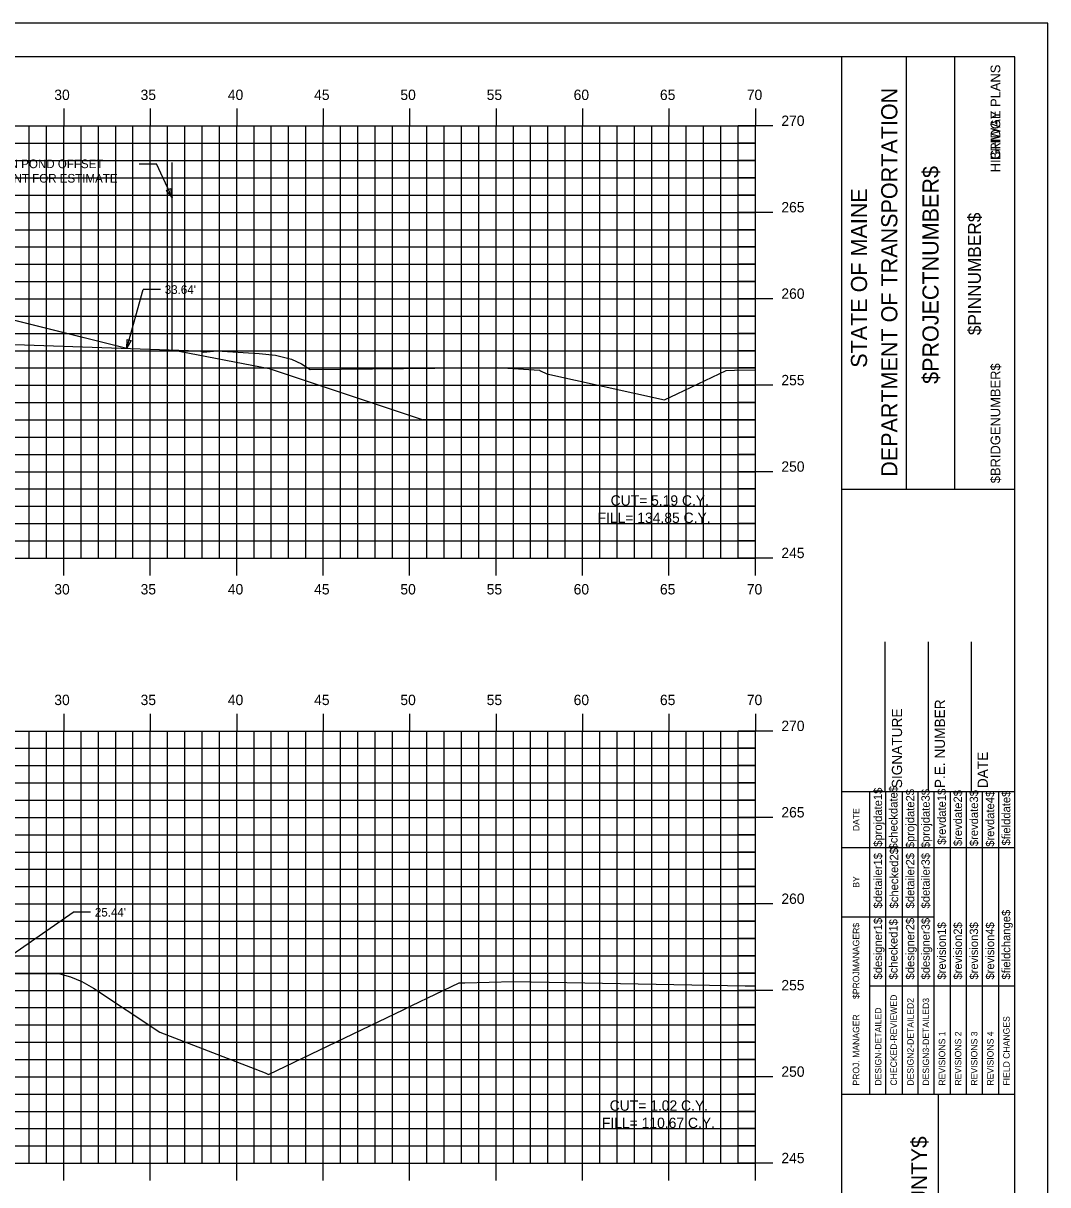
# Model space of a CAD drawing. Extents: x 1170543 to 1177585, y 609599 to 610623.
# Drawn here: x 1175606.5 to 1175665.7, y 609641.6 to 609708.8 of the extents above; entities that cross this region are included whole.
import ezdxf

# ---------------------------------------------------------------- set-up
doc = ezdxf.new("R2010")
doc.units = 0
for name, color, linetype in [('ANNOTATION', 7, 'Continuous'), ('BORDER', 7, 'Continuous'), ('BRIDGE_TITLE', 7, 'Continuous'), ('D_Roadway_Centerline', 7, 'Continuous'), ('D_Roadway_Centerline_Text', 7, 'Continuous'), ('D_Roadway_Edge_Pavement', 7, 'Continuous'), ('D_Roadway_Pavement', 7, 'Continuous'), ('D_Roadway_SlopeLines', 7, 'Continuous'), ('H_V ANNOTATION', 7, 'Continuous'), ('HIGHWAY_TITLE', 7, 'Continuous'), ('MAJOR', 7, 'Continuous'), ('MINOR', 7, 'Continuous'), ('PLOT BOUNDARY', 7, 'Continuous'), ('S_Roadway_Centerline', 7, 'Continuous')]:
    doc.layers.add(name, color=color, linetype=linetype)

msp = doc.modelspace()

# ---------------------------------------------------------------- linework, layer by layer
at = {"layer": 'ANNOTATION'}
for p, q in [((1175613.193, 609700.68), (1175614.193, 609700.68)), ((1175615.096, 609698.739), (1175614.193, 609700.68)), ((1175612.469, 609690.009), (1175613.414, 609693.408)), ((1175614.414, 609693.408), (1175613.414, 609693.408)), ((1175604.272, 609653.849), (1175609.374, 609657.391)), ((1175610.374, 609657.391), (1175609.374, 609657.391))]:
    msp.add_line(p, q, dxfattribs=at)
for points in [[(1175614.999, 609699.245), (1175615.096, 609698.739), (1175614.772, 609699.14)], [(1175612.723, 609690.457), (1175612.469, 609690.009), (1175612.483, 609690.524)]]:
    msp.add_lwpolyline(points, close=True, dxfattribs=at)
at = {"layer": 'BORDER'}
for p, q in [((1175663.826, 609706.872), (1175503.826, 609706.872)), ((1175653.826, 609601.875), (1175653.826, 609706.875)), ((1175657.555, 609681.869), (1175657.555, 609706.869)), ((1175660.35, 609681.869), (1175660.35, 609706.869)), ((1175663.826, 609601.875), (1175663.826, 609706.875)), ((1175653.827, 609681.866), (1175663.826, 609681.866)), ((1175656.326, 609664.375), (1175656.326, 609673.023)), ((1175658.826, 609664.375), (1175658.826, 609673.023)), ((1175661.326, 609664.375), (1175661.326, 609673.023)), ((1175653.826, 609664.375), (1175663.826, 609664.375)), ((1175653.826, 609646.875), (1175663.826, 609646.875)), ((1175659.417, 609611.875), (1175659.417, 609646.875))]:
    msp.add_line(p, q, dxfattribs=at)
for points in [[(1175655.441, 609661.125), (1175655.441, 609664.375)], [(1175656.374, 609646.878), (1175656.374, 609664.375)], [(1175657.305, 609664.375), (1175657.305, 609646.878)], [(1175658.237, 609646.878), (1175658.237, 609664.375)], [(1175659.169, 609646.878), (1175659.169, 609664.375)], [(1175660.101, 609646.878), (1175660.101, 609664.375)], [(1175661.032, 609646.878), (1175661.032, 609664.375)], [(1175661.964, 609646.878), (1175661.964, 609664.375)], [(1175662.896, 609646.878), (1175662.896, 609664.375)], [(1175655.442, 609646.878), (1175655.442, 609663.669)], [(1175653.826, 609661.125), (1175663.826, 609661.125)], [(1175653.826, 609657.125), (1175655.442, 609657.125)], [(1175655.441, 609657.125), (1175659.168, 609657.125)], [(1175655.441, 609653.125), (1175663.826, 609653.125)]]:
    msp.add_lwpolyline(points, dxfattribs=at)
at = {"layer": 'D_Roadway_Centerline'}
for p, q in [((1175597.826, 609693.67), (1175606.919, 609691.397)), ((1175606.919, 609691.397), (1175612.469, 609690.009))]:
    msp.add_line(p, q, dxfattribs=at)
at = {"layer": 'D_Roadway_Edge_Pavement'}
msp.add_line((1175648.826, 609685.872), (1175629.617, 609685.872), dxfattribs=at)
msp.add_lwpolyline([(1175615.096, 609689.92), (1175620.706, 609688.839), (1175621.974, 609688.417), (1175623.709, 609687.839), (1175624.986, 609687.414), (1175626.712, 609686.839), (1175629.617, 609685.872)], dxfattribs=at)
at = {"layer": 'D_Roadway_Pavement'}
msp.add_line((1175615.096, 609689.925), (1175615.096, 609700.765), dxfattribs=at)
at = {"layer": 'D_Roadway_SlopeLines'}
msp.add_lwpolyline([(1175597.826, 609693.67), (1175612.469, 609690.009)], dxfattribs=at)
at = {"layer": 'MAJOR'}
for p, q in [((1175608.826, 609703.874), (1175608.826, 609702.872)), ((1175613.826, 609703.874), (1175613.826, 609702.872)), ((1175618.826, 609703.874), (1175618.826, 609702.872)), ((1175623.826, 609703.874), (1175623.826, 609702.872)), ((1175628.826, 609703.874), (1175628.826, 609702.872)), ((1175633.826, 609703.874), (1175633.826, 609702.872)), ((1175638.826, 609703.874), (1175638.826, 609702.872)), ((1175643.826, 609703.874), (1175643.826, 609702.872)), ((1175648.826, 609703.874), (1175648.826, 609702.872)), ((1175508.826, 609702.872), (1175648.826, 609702.872)), ((1175508.826, 609702.872), (1175648.826, 609702.872)), ((1175608.826, 609677.872), (1175608.826, 609702.872)), ((1175613.826, 609677.872), (1175613.826, 609702.872)), ((1175618.826, 609677.872), (1175618.826, 609702.872)), ((1175623.826, 609677.872), (1175623.826, 609702.872)), ((1175628.826, 609677.872), (1175628.826, 609702.872)), ((1175633.826, 609677.872), (1175633.826, 609702.872)), ((1175638.826, 609677.872), (1175638.826, 609702.872)), ((1175643.826, 609677.872), (1175643.826, 609702.872)), ((1175649.828, 609702.872), (1175647.824, 609702.872)), ((1175648.826, 609677.872), (1175648.826, 609702.872)), ((1175648.826, 609677.872), (1175648.826, 609702.872)), ((1175508.826, 609697.872), (1175648.826, 609697.872)), ((1175649.828, 609697.872), (1175647.824, 609697.872)), ((1175508.826, 609692.872), (1175648.826, 609692.872)), ((1175649.828, 609692.872), (1175647.824, 609692.872)), ((1175508.826, 609687.872), (1175648.826, 609687.872)), ((1175649.828, 609687.872), (1175647.824, 609687.872)), ((1175508.826, 609682.872), (1175648.826, 609682.872)), ((1175649.828, 609682.872), (1175647.824, 609682.872)), ((1175508.826, 609677.872), (1175648.826, 609677.872)), ((1175508.826, 609677.872), (1175648.826, 609677.872)), ((1175608.826, 609676.87), (1175608.826, 609677.872)), ((1175613.826, 609676.87), (1175613.826, 609677.872)), ((1175618.826, 609676.87), (1175618.826, 609677.872)), ((1175623.826, 609676.87), (1175623.826, 609677.872)), ((1175628.826, 609676.87), (1175628.826, 609677.872)), ((1175633.826, 609676.87), (1175633.826, 609677.872)), ((1175638.826, 609676.87), (1175638.826, 609677.872)), ((1175643.826, 609676.87), (1175643.826, 609677.872)), ((1175649.828, 609677.872), (1175647.824, 609677.872)), ((1175648.826, 609676.87), (1175648.826, 609677.872)), ((1175608.826, 609668.874), (1175608.826, 609667.872)), ((1175613.826, 609668.874), (1175613.826, 609667.872)), ((1175618.826, 609668.874), (1175618.826, 609667.872)), ((1175623.826, 609668.874), (1175623.826, 609667.872)), ((1175628.826, 609668.874), (1175628.826, 609667.872)), ((1175633.826, 609668.874), (1175633.826, 609667.872)), ((1175638.826, 609668.874), (1175638.826, 609667.872)), ((1175643.826, 609668.874), (1175643.826, 609667.872)), ((1175648.826, 609668.874), (1175648.826, 609667.872)), ((1175508.826, 609667.872), (1175648.826, 609667.872)), ((1175508.826, 609667.872), (1175648.826, 609667.872)), ((1175608.826, 609642.872), (1175608.826, 609667.872)), ((1175613.826, 609642.872), (1175613.826, 609667.872)), ((1175618.826, 609642.872), (1175618.826, 609667.872)), ((1175623.826, 609642.872), (1175623.826, 609667.872)), ((1175628.826, 609642.872), (1175628.826, 609667.872)), ((1175633.826, 609642.872), (1175633.826, 609667.872)), ((1175638.826, 609642.872), (1175638.826, 609667.872)), ((1175643.826, 609642.872), (1175643.826, 609667.872)), ((1175649.828, 609667.872), (1175647.824, 609667.872)), ((1175648.826, 609642.872), (1175648.826, 609667.872)), ((1175648.826, 609642.872), (1175648.826, 609667.872)), ((1175508.826, 609662.872), (1175648.826, 609662.872)), ((1175649.828, 609662.872), (1175647.824, 609662.872)), ((1175508.826, 609657.872), (1175648.826, 609657.872)), ((1175649.828, 609657.872), (1175647.824, 609657.872)), ((1175508.826, 609652.872), (1175648.826, 609652.872)), ((1175649.828, 609652.872), (1175647.824, 609652.872)), ((1175508.826, 609647.872), (1175648.826, 609647.872)), ((1175649.828, 609647.872), (1175647.824, 609647.872)), ((1175508.826, 609642.872), (1175648.826, 609642.872)), ((1175508.826, 609642.872), (1175648.826, 609642.872)), ((1175608.826, 609641.87), (1175608.826, 609642.872)), ((1175613.826, 609641.87), (1175613.826, 609642.872)), ((1175618.826, 609641.87), (1175618.826, 609642.872)), ((1175623.826, 609641.87), (1175623.826, 609642.872)), ((1175628.826, 609641.87), (1175628.826, 609642.872)), ((1175633.826, 609641.87), (1175633.826, 609642.872)), ((1175638.826, 609641.87), (1175638.826, 609642.872)), ((1175643.826, 609641.87), (1175643.826, 609642.872)), ((1175649.828, 609642.872), (1175647.824, 609642.872)), ((1175648.826, 609641.87), (1175648.826, 609642.872))]:
    msp.add_line(p, q, dxfattribs=at)
at = {"layer": 'MINOR'}
for p, q in [((1175606.826, 609677.872), (1175606.826, 609702.872)), ((1175607.826, 609677.872), (1175607.826, 609702.872)), ((1175609.826, 609677.872), (1175609.826, 609702.872)), ((1175610.826, 609677.872), (1175610.826, 609702.872)), ((1175611.826, 609677.872), (1175611.826, 609702.872)), ((1175612.826, 609677.872), (1175612.826, 609702.872)), ((1175614.826, 609677.872), (1175614.826, 609702.872)), ((1175615.826, 609677.872), (1175615.826, 609702.872)), ((1175616.826, 609677.872), (1175616.826, 609702.872)), ((1175617.826, 609677.872), (1175617.826, 609702.872)), ((1175619.826, 609677.872), (1175619.826, 609702.872)), ((1175620.826, 609677.872), (1175620.826, 609702.872)), ((1175621.826, 609677.872), (1175621.826, 609702.872)), ((1175622.826, 609677.872), (1175622.826, 609702.872)), ((1175624.826, 609677.872), (1175624.826, 609702.872)), ((1175625.826, 609677.872), (1175625.826, 609702.872)), ((1175626.826, 609677.872), (1175626.826, 609702.872)), ((1175627.826, 609677.872), (1175627.826, 609702.872)), ((1175629.826, 609677.872), (1175629.826, 609702.872)), ((1175630.826, 609677.872), (1175630.826, 609702.872)), ((1175631.826, 609677.872), (1175631.826, 609702.872)), ((1175632.826, 609677.872), (1175632.826, 609702.872)), ((1175634.826, 609677.872), (1175634.826, 609702.872)), ((1175635.826, 609677.872), (1175635.826, 609702.872)), ((1175636.826, 609677.872), (1175636.826, 609702.872)), ((1175637.826, 609677.872), (1175637.826, 609702.872)), ((1175639.826, 609677.872), (1175639.826, 609702.872)), ((1175640.826, 609677.872), (1175640.826, 609702.872)), ((1175641.826, 609677.872), (1175641.826, 609702.872)), ((1175642.826, 609677.872), (1175642.826, 609702.872)), ((1175644.826, 609677.872), (1175644.826, 609702.872)), ((1175645.826, 609677.872), (1175645.826, 609702.872)), ((1175646.826, 609677.872), (1175646.826, 609702.872)), ((1175647.826, 609677.872), (1175647.826, 609702.872)), ((1175508.826, 609701.872), (1175648.826, 609701.872)), ((1175648.826, 609701.872), (1175647.824, 609701.872)), ((1175508.826, 609700.872), (1175648.826, 609700.872)), ((1175648.826, 609700.872), (1175647.824, 609700.872)), ((1175508.826, 609699.872), (1175648.826, 609699.872)), ((1175648.826, 609699.872), (1175647.824, 609699.872)), ((1175508.826, 609698.872), (1175648.826, 609698.872)), ((1175648.826, 609698.872), (1175647.824, 609698.872)), ((1175508.826, 609696.872), (1175648.826, 609696.872)), ((1175648.826, 609696.872), (1175647.824, 609696.872)), ((1175508.826, 609695.872), (1175648.826, 609695.872)), ((1175648.826, 609695.872), (1175647.824, 609695.872)), ((1175508.826, 609694.872), (1175648.826, 609694.872)), ((1175648.826, 609694.872), (1175647.824, 609694.872)), ((1175508.826, 609693.872), (1175648.826, 609693.872)), ((1175648.826, 609693.872), (1175647.824, 609693.872)), ((1175508.826, 609691.872), (1175648.826, 609691.872)), ((1175648.826, 609691.872), (1175647.824, 609691.872)), ((1175508.826, 609690.872), (1175648.826, 609690.872)), ((1175648.826, 609690.872), (1175647.824, 609690.872)), ((1175508.826, 609689.872), (1175648.826, 609689.872)), ((1175648.826, 609689.872), (1175647.824, 609689.872)), ((1175508.826, 609688.872), (1175648.826, 609688.872)), ((1175648.826, 609688.872), (1175647.824, 609688.872)), ((1175508.826, 609686.872), (1175648.826, 609686.872)), ((1175648.826, 609686.872), (1175647.824, 609686.872)), ((1175508.826, 609685.872), (1175648.826, 609685.872)), ((1175648.826, 609685.872), (1175647.824, 609685.872)), ((1175508.826, 609684.872), (1175648.826, 609684.872)), ((1175648.826, 609684.872), (1175647.824, 609684.872)), ((1175508.826, 609683.872), (1175648.826, 609683.872)), ((1175648.826, 609683.872), (1175647.824, 609683.872)), ((1175508.826, 609681.872), (1175648.826, 609681.872)), ((1175648.826, 609681.872), (1175647.824, 609681.872)), ((1175508.826, 609680.872), (1175648.826, 609680.872)), ((1175648.826, 609680.872), (1175647.824, 609680.872)), ((1175508.826, 609679.872), (1175648.826, 609679.872)), ((1175648.826, 609679.872), (1175647.824, 609679.872)), ((1175508.826, 609678.872), (1175648.826, 609678.872)), ((1175648.826, 609678.872), (1175647.824, 609678.872)), ((1175606.826, 609642.872), (1175606.826, 609667.872)), ((1175607.826, 609642.872), (1175607.826, 609667.872)), ((1175609.826, 609642.872), (1175609.826, 609667.872)), ((1175610.826, 609642.872), (1175610.826, 609667.872)), ((1175611.826, 609642.872), (1175611.826, 609667.872)), ((1175612.826, 609642.872), (1175612.826, 609667.872)), ((1175614.826, 609642.872), (1175614.826, 609667.872)), ((1175615.826, 609642.872), (1175615.826, 609667.872)), ((1175616.826, 609642.872), (1175616.826, 609667.872)), ((1175617.826, 609642.872), (1175617.826, 609667.872)), ((1175619.826, 609642.872), (1175619.826, 609667.872)), ((1175620.826, 609642.872), (1175620.826, 609667.872)), ((1175621.826, 609642.872), (1175621.826, 609667.872)), ((1175622.826, 609642.872), (1175622.826, 609667.872)), ((1175624.826, 609642.872), (1175624.826, 609667.872)), ((1175625.826, 609642.872), (1175625.826, 609667.872)), ((1175626.826, 609642.872), (1175626.826, 609667.872)), ((1175627.826, 609642.872), (1175627.826, 609667.872)), ((1175629.826, 609642.872), (1175629.826, 609667.872)), ((1175630.826, 609642.872), (1175630.826, 609667.872)), ((1175631.826, 609642.872), (1175631.826, 609667.872)), ((1175632.826, 609642.872), (1175632.826, 609667.872)), ((1175634.826, 609642.872), (1175634.826, 609667.872)), ((1175635.826, 609642.872), (1175635.826, 609667.872)), ((1175636.826, 609642.872), (1175636.826, 609667.872)), ((1175637.826, 609642.872), (1175637.826, 609667.872)), ((1175639.826, 609642.872), (1175639.826, 609667.872)), ((1175640.826, 609642.872), (1175640.826, 609667.872)), ((1175641.826, 609642.872), (1175641.826, 609667.872)), ((1175642.826, 609642.872), (1175642.826, 609667.872)), ((1175644.826, 609642.872), (1175644.826, 609667.872)), ((1175645.826, 609642.872), (1175645.826, 609667.872)), ((1175646.826, 609642.872), (1175646.826, 609667.872)), ((1175647.826, 609642.872), (1175647.826, 609667.872)), ((1175508.826, 609666.872), (1175648.826, 609666.872)), ((1175648.826, 609666.872), (1175647.824, 609666.872)), ((1175508.826, 609665.872), (1175648.826, 609665.872)), ((1175648.826, 609665.872), (1175647.824, 609665.872)), ((1175508.826, 609664.872), (1175648.826, 609664.872)), ((1175648.826, 609664.872), (1175647.824, 609664.872)), ((1175508.826, 609663.872), (1175648.826, 609663.872)), ((1175648.826, 609663.872), (1175647.824, 609663.872)), ((1175508.826, 609661.872), (1175648.826, 609661.872)), ((1175648.826, 609661.872), (1175647.824, 609661.872)), ((1175508.826, 609660.872), (1175648.826, 609660.872)), ((1175648.826, 609660.872), (1175647.824, 609660.872)), ((1175508.826, 609659.872), (1175648.826, 609659.872)), ((1175648.826, 609659.872), (1175647.824, 609659.872)), ((1175508.826, 609658.872), (1175648.826, 609658.872)), ((1175648.826, 609658.872), (1175647.824, 609658.872)), ((1175508.826, 609656.872), (1175648.826, 609656.872)), ((1175648.826, 609656.872), (1175647.824, 609656.872)), ((1175508.826, 609655.872), (1175648.826, 609655.872)), ((1175648.826, 609655.872), (1175647.824, 609655.872)), ((1175508.826, 609654.872), (1175648.826, 609654.872)), ((1175648.826, 609654.872), (1175647.824, 609654.872)), ((1175508.826, 609653.872), (1175648.826, 609653.872)), ((1175648.826, 609653.872), (1175647.824, 609653.872)), ((1175508.826, 609651.872), (1175648.826, 609651.872)), ((1175648.826, 609651.872), (1175647.824, 609651.872)), ((1175508.826, 609650.872), (1175648.826, 609650.872)), ((1175648.826, 609650.872), (1175647.824, 609650.872)), ((1175508.826, 609649.872), (1175648.826, 609649.872)), ((1175648.826, 609649.872), (1175647.824, 609649.872)), ((1175508.826, 609648.872), (1175648.826, 609648.872)), ((1175648.826, 609648.872), (1175647.824, 609648.872)), ((1175508.826, 609646.872), (1175648.826, 609646.872)), ((1175648.826, 609646.872), (1175647.824, 609646.872)), ((1175508.826, 609645.872), (1175648.826, 609645.872)), ((1175648.826, 609645.872), (1175647.824, 609645.872)), ((1175508.826, 609644.872), (1175648.826, 609644.872)), ((1175648.826, 609644.872), (1175647.824, 609644.872)), ((1175508.826, 609643.872), (1175648.826, 609643.872)), ((1175648.826, 609643.872), (1175647.824, 609643.872))]:
    msp.add_line(p, q, dxfattribs=at)
at = {"layer": 'PLOT BOUNDARY'}
msp.add_lwpolyline([(1175495.733, 609598.813), (1175665.733, 609598.813), (1175665.733, 609708.813), (1175495.733, 609708.813)], close=True, dxfattribs=at)
at = {"layer": 'S_Roadway_Centerline'}
for points in [[(1175590.357, 609690.761), (1175616.588, 609689.869), (1175616.667, 609689.864), (1175616.745, 609689.85), (1175616.822, 609689.826), (1175616.898, 609689.793), (1175617.677, 609689.862), (1175620.115, 609689.717), (1175621.066, 609689.606), (1175621.917, 609689.41), (1175621.989, 609689.389), (1175622.564, 609689.116), (1175623.065, 609688.785), (1175633.884, 609688.897), (1175636.333, 609688.745), (1175636.38, 609688.706), (1175636.386, 609688.709), (1175636.756, 609688.532), (1175643.568, 609687.02), (1175644.302, 609687.372), (1175647.135, 609688.729), (1175647.611, 609688.739), (1175648.826, 609688.764)], [(1175601.764, 609653.867), (1175608.6, 609653.818), (1175609.22, 609653.657), (1175609.867, 609653.384), (1175610.544, 609652.989), (1175614.375, 609650.458), (1175620.465, 609648.102), (1175620.669, 609648.011), (1175628.491, 609651.769), (1175628.946, 609651.987), (1175631.698, 609653.309), (1175632.025, 609653.316), (1175634.838, 609653.377), (1175648.238, 609653.136), (1175648.826, 609653.138)]]:
    msp.add_lwpolyline(points, dxfattribs=at)

# ---------------------------------------------------------------- texts
at = {"layer": 'ANNOTATION'}
for s, p in [('DETENTION POND OFFSET', (1175602.313, 609700.43)), ('BREAK POINT FOR ESTIMATE', (1175602.313, 609699.595)), ("33.64'", (1175614.664, 609693.158)), ("25.44'", (1175610.624, 609657.141))]:
    msp.add_text(s, height=0.5, dxfattribs=at).set_placement(p)
at = {"layer": 'BORDER'}
for s, height, p in [('DEPARTMENT OF TRANSPORTATION', 0.93176, (1175657.033, 609682.578)), ('$PROJECTNUMBER$', 0.93176, (1175659.418, 609687.951)), ('STATE OF MAINE', 0.93176, (1175655.282, 609688.884)), ('$PINNUMBER$', 0.74527, (1175661.863, 609690.769)), ('SIGNATURE', 0.5906, (1175657.307, 609664.567)), ('P.E. NUMBER', 0.59055, (1175659.787, 609664.567)), ('DATE', 0.5906, (1175662.267, 609664.567)), ('$projdate1$', 0.48455, (1175656.149, 609661.176)), ('$checkdate$', 0.48455, (1175657.044, 609661.018)), ('$projdate2$', 0.48455, (1175658.013, 609661.097)), ('$projdate3$', 0.48455, (1175658.907, 609661.097)), ('$revdate1$', 0.4845, (1175659.839, 609661.294)), ('$revdate2$', 0.4845, (1175660.77, 609661.215)), ('$revdate3$', 0.4845, (1175661.702, 609661.215)), ('$revdate4$', 0.4845, (1175662.634, 609661.176)), ('$fielddate$', 0.48455, (1175663.565, 609661.254)), ('DATE', 0.3714, (1175654.831, 609662.081)), ('$checked2$', 0.4845, (1175657.081, 609657.61)), ('$detailer1$', 0.48455, (1175656.149, 609657.61)), ('$detailer2$', 0.48455, (1175658.013, 609657.61)), ('$detailer3$', 0.48455, (1175658.907, 609657.61)), ('BY', 0.3714, (1175654.831, 609658.81)), ('$designer1$', 0.48455, (1175656.149, 609653.498)), ('$designer2$', 0.48455, (1175658.013, 609653.498)), ('$designer3$', 0.48455, (1175658.907, 609653.498)), ('$fieldchange$', 0.48455, (1175663.565, 609653.498)), ('$PROJMANAGER$', 0.37275, (1175654.831, 609652.37)), ('$checked1$', 0.4845, (1175657.044, 609653.498)), ('$revision1$', 0.48455, (1175659.839, 609653.498)), ('$revision2$', 0.48455, (1175660.77, 609653.498)), ('$revision3$', 0.48455, (1175661.702, 609653.498)), ('$revision4$', 0.48455, (1175662.634, 609653.498)), ('CHECKED-REVIEWED', 0.37275, (1175657.007, 609647.363)), ('DESIGN2-DETAILED2', 0.37275, (1175657.976, 609647.363)), ('DESIGN3-DETAILED3', 0.37275, (1175658.871, 609647.363)), ('DESIGN-DETAILED', 0.37275, (1175656.113, 609647.363)), ('PROJ. MANAGER', 0.37275, (1175654.831, 609647.363)), ('FIELD CHANGES', 0.37275, (1175663.529, 609647.363)), ('REVISIONS 1', 0.37275, (1175659.802, 609647.363)), ('REVISIONS 2', 0.37275, (1175660.734, 609647.363)), ('REVISIONS 3', 0.37275, (1175661.666, 609647.363)), ('REVISIONS 4', 0.37275, (1175662.597, 609647.363))]:
    msp.add_text(s, height=height, rotation=90, dxfattribs=at).set_placement(p)
at = {"layer": 'BRIDGE_TITLE'}
for s, height, p in [('BRIDGE PLANS', 0.55901, (1175662.985, 609700.897)), ('$BRIDGENUMBER$', 0.55901, (1175662.985, 609682.203)), ('$COUNTY$', 0.9072, (1175658.747, 609637.954))]:
    msp.add_text(s, height=height, rotation=90, dxfattribs=at).set_placement(p)
at = {"layer": 'D_Roadway_Centerline_Text'}
for s, p in [('CUT= 5.19 C.Y.', (1175640.452, 609680.908)), ('FILL= 134.85 C.Y.', (1175639.698, 609679.906)), ('CUT= 1.02 C.Y.', (1175640.399, 609645.908)), ('FILL= 110.67 C.Y.', (1175639.95, 609644.906))]:
    msp.add_text(s, height=0.6, dxfattribs=at).set_placement(p)
at = {"layer": 'H_V ANNOTATION'}
for s, p in [('30', (1175608.275, 609704.372)), ('35', (1175613.267, 609704.372)), ('40', (1175618.312, 609704.372)), ('45', (1175623.304, 609704.372)), ('50', (1175628.291, 609704.372)), ('55', (1175633.283, 609704.372)), ('60', (1175638.312, 609704.372)), ('65', (1175643.304, 609704.372)), ('70', (1175648.328, 609704.372)), ('270', (1175650.326, 609702.872)), ('265', (1175650.326, 609697.872)), ('260', (1175650.326, 609692.872)), ('255', (1175650.326, 609687.872)), ('250', (1175650.326, 609682.872)), ('245', (1175650.326, 609677.872)), ('30', (1175608.275, 609675.772)), ('35', (1175613.267, 609675.772)), ('40', (1175618.312, 609675.772)), ('45', (1175623.304, 609675.772)), ('50', (1175628.291, 609675.772)), ('55', (1175633.283, 609675.772)), ('60', (1175638.312, 609675.772)), ('65', (1175643.304, 609675.772)), ('70', (1175648.328, 609675.772)), ('30', (1175608.275, 609669.372)), ('35', (1175613.267, 609669.372)), ('40', (1175618.312, 609669.372)), ('45', (1175623.304, 609669.372)), ('50', (1175628.291, 609669.372)), ('55', (1175633.283, 609669.372)), ('60', (1175638.312, 609669.372)), ('65', (1175643.304, 609669.372)), ('70', (1175648.328, 609669.372)), ('270', (1175650.326, 609667.872)), ('265', (1175650.326, 609662.872)), ('260', (1175650.326, 609657.872)), ('255', (1175650.326, 609652.872)), ('250', (1175650.326, 609647.872)), ('245', (1175650.326, 609642.872))]:
    msp.add_text(s, height=0.6, dxfattribs=at).set_placement(p)
at = {"layer": 'HIGHWAY_TITLE'}
msp.add_text('HIGHWAY PLANS', height=0.55901, rotation=90, dxfattribs=at).set_placement((1175662.985, 609700.188))

doc.saveas('drawing.dxf')
